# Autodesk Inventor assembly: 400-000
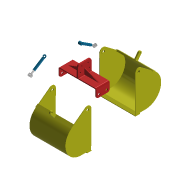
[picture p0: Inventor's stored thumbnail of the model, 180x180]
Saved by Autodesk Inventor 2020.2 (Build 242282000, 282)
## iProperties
Created: 2014-01
Part Number: 400-000
Document SubType Name: Assembly
Designer: F.Stasiak
Manager: www.cadconsulting.pl
Company: Fabian Stasiak CAD Consulting
Author: F.Stasiak
Subject: Zbiór ćwiczeń. Autodesk Inventor 2020. Kurs podstawowy
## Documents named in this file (4)
- C:\2020_Kurs_podstawowy\R6 Zespoły\Warsztat\400-000.iam
- C:\2020_Kurs_podstawowy\R6 Zespoły\Warsztat\Komponenty\400-001.ipt
- C:\2020_Kurs_podstawowy\R6 Zespoły\Warsztat\Komponenty\400-002.ipt
- C:\2020_Kurs_podstawowy\R6 Zespoły\Warsztat\Komponenty\S-100.iam
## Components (5 placed, 3 different names)
1. 400-001:1
2. 400-002:1
3. 400-002:2
4. S-100:2 [sub-assembly]
5. S-100:3 [sub-assembly]
